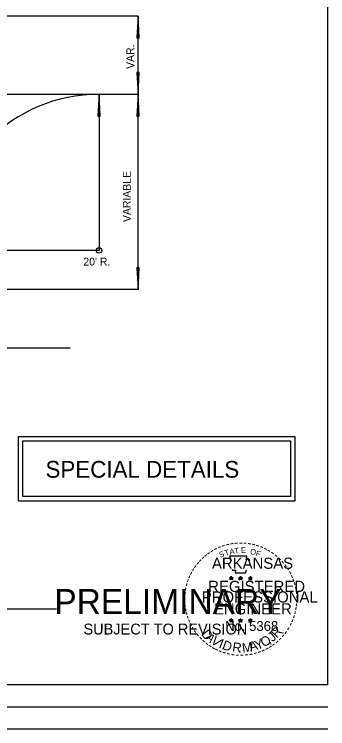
# Model space of a CAD drawing. Extents: x 1944905 to 1956777, y 763871 to 764977.
# Drawn here: x 1947951 to 1948232, y 763871 to 764511 of the extents above; entities that cross this region are included whole.
import ezdxf

# ---------------------------------------------------------------- set-up
doc = ezdxf.new("R2010")
doc.units = 0
for name, color, linetype in [('Default', 7, 'Continuous'), ('E_Existing ROW', 7, 'Continuous'), ('R_Border PE', 7, 'Continuous')]:
    doc.layers.add(name, color=color, linetype=linetype)

msp = doc.modelspace()

# ---------------------------------------------------------------- linework, layer by layer
at = {"layer": 'Default'}
for p, q in [((1948232.12, 763910.07), (1948232.12, 764937.29)), ((1948061.85, 764509.29), (1947543.85, 764509.29)), ((1948061.85, 764509.29), (1948060.88, 764489.74)), ((1948061.85, 764439.29), (1948061.85, 764509.29)), ((1948062.83, 764489.74), (1948061.85, 764509.29)), ((1948060.88, 764489.74), (1948062.83, 764489.74)), ((1948062.83, 764489.68), (1948062.83, 764489.74)), ((1948060.88, 764458.9), (1948060.88, 764458.84)), ((1948060.88, 764458.84), (1948061.85, 764439.29)), ((1948062.83, 764458.84), (1948060.88, 764458.84)), ((1948061.85, 764439.29), (1948062.83, 764458.84)), ((1947578.85, 764439.29), (1948026.85, 764439.29)), ((1948026.85, 764439.29), (1948025.88, 764419.74)), ((1948027.83, 764419.74), (1948026.85, 764439.29)), ((1948026.85, 764439.29), (1948026.85, 764299.29)), ((1948061.85, 764439.29), (1948060.88, 764419.74)), ((1948062.83, 764419.74), (1948061.85, 764439.29)), ((1948061.85, 764264.29), (1948061.85, 764438.7)), ((1948025.88, 764419.74), (1948027.83, 764419.74)), ((1948027.83, 764419.68), (1948027.83, 764419.74)), ((1948060.88, 764419.74), (1948062.83, 764419.74)), ((1948062.83, 764419.68), (1948062.83, 764419.74)), ((1948026.85, 764299.29), (1947886.85, 764299.29)), ((1948060.88, 764283.9), (1948060.88, 764283.84)), ((1948060.88, 764283.84), (1948061.85, 764264.29)), ((1948062.83, 764283.84), (1948060.88, 764283.84)), ((1948061.85, 764264.29), (1948062.83, 764283.84)), ((1948061.85, 764264.29), (1947886.85, 764264.29)), ((1947605.64, 764211.94), (1948001.01, 764211.94)), ((1947592.86, 763978), (1947988.57, 763978)), ((1948232.12, 763910.07), (1946651.22, 763910.07)), ((1946618.38, 763890.36), (1948232.12, 763890.36)), ((1946618.38, 763870.67), (1948232.12, 763870.67))]:
    msp.add_line(p, q, dxfattribs=at)
for points in [[(1947954.62, 764132.69), (1948202.63, 764132.69), (1948202.63, 764074.65), (1947954.62, 764074.65)], [(1947958.62, 764128.69), (1948198.63, 764128.69), (1948198.63, 764078.65), (1947958.62, 764078.65)]]:
    msp.add_lwpolyline(points, close=True, dxfattribs=at)
msp.add_circle((1948026.85, 764299.29), 2.44, dxfattribs=at)
at = {"layer": 'E_Existing ROW'}
msp.add_line((1948026.85, 764439.29), (1948061.85, 764439.29), dxfattribs=at)
msp.add_arc((1948026.85, 764299.29), 140, 90, 180, dxfattribs=at)
at = {"layer": 'R_Border PE'}
for p, q in [((1948143.78, 764006.04), (1948145.48, 764005.49)), ((1948143.78, 764006.04), (1948145.03, 764005.89)), ((1948143.78, 764006.04), (1948145.03, 764005.84)), ((1948143.78, 764006.04), (1948144.98, 764005.74)), ((1948143.78, 764006.04), (1948144.98, 764005.54)), ((1948143.78, 764006.04), (1948144.93, 764005.44)), ((1948143.78, 764006.04), (1948144.93, 764005.34)), ((1948144.43, 764003.99), (1948145.48, 764005.49)), ((1948144.43, 764003.99), (1948144.98, 764005.39)), ((1948144.43, 764003.99), (1948145.03, 764005.24)), ((1948144.43, 764003.99), (1948145.13, 764005.19)), ((1948144.43, 764003.99), (1948145.48, 764005.09)), ((1948144.43, 764003.99), (1948145.28, 764005.04)), ((1948144.43, 764003.99), (1948145.53, 764004.94)), ((1948145.48, 764007.29), (1948145.23, 764006.09)), ((1948145.48, 764007.29), (1948145.28, 764006.04)), ((1948145.48, 764007.29), (1948145.43, 764006.04)), ((1948145.48, 764005.49), (1948145.48, 764007.29)), ((1948145.48, 764007.29), (1948145.83, 764006.04)), ((1948145.48, 764007.29), (1948145.73, 764006.04)), ((1948145.48, 764007.29), (1948145.63, 764006.09)), ((1948147.23, 764006.04), (1948145.48, 764005.49)), ((1948146.58, 764003.99), (1948145.48, 764005.49)), ((1948146.58, 764003.99), (1948145.48, 764005.09)), ((1948146.58, 764003.99), (1948145.48, 764004.94)), ((1948146.58, 764003.99), (1948145.68, 764005.04)), ((1948147.23, 764006.04), (1948145.73, 764005.94)), ((1948147.23, 764006.04), (1948145.83, 764005.79)), ((1948147.23, 764006.04), (1948145.83, 764005.69)), ((1948146.58, 764003.99), (1948145.83, 764005.24)), ((1948146.58, 764003.99), (1948145.88, 764005.44)), ((1948146.58, 764003.99), (1948145.98, 764005.44)), ((1948147.23, 764006.04), (1948146.13, 764005.59)), ((1948147.23, 764006.04), (1948146.23, 764005.54)), ((1948147.23, 764006.04), (1948146.28, 764005.49)), ((1948152.08, 764006.04), (1948153.83, 764005.49)), ((1948152.08, 764006.04), (1948153.38, 764005.89)), ((1948152.08, 764006.04), (1948153.38, 764005.84)), ((1948152.08, 764006.04), (1948153.33, 764005.74)), ((1948152.08, 764006.04), (1948153.33, 764005.54)), ((1948152.08, 764006.04), (1948153.28, 764005.44)), ((1948152.08, 764006.04), (1948153.28, 764005.34)), ((1948152.78, 764003.99), (1948153.83, 764005.49)), ((1948152.78, 764003.99), (1948153.33, 764005.39)), ((1948152.78, 764003.99), (1948153.38, 764005.24)), ((1948152.78, 764003.99), (1948153.48, 764005.19)), ((1948152.78, 764003.99), (1948153.83, 764005.09)), ((1948152.78, 764003.99), (1948153.63, 764005.04)), ((1948152.78, 764003.99), (1948153.88, 764004.94)), ((1948153.83, 764007.29), (1948153.58, 764006.09)), ((1948153.83, 764007.29), (1948153.63, 764006.04)), ((1948153.83, 764007.29), (1948153.78, 764006.04)), ((1948153.83, 764005.49), (1948153.83, 764007.29)), ((1948153.83, 764007.29), (1948154.18, 764006.04)), ((1948153.83, 764007.29), (1948154.08, 764006.04)), ((1948153.83, 764007.29), (1948153.98, 764006.09)), ((1948155.58, 764006.04), (1948153.83, 764005.49)), ((1948154.93, 764003.99), (1948153.83, 764005.49)), ((1948154.93, 764003.99), (1948153.83, 764005.09)), ((1948154.93, 764003.99), (1948153.83, 764004.94)), ((1948155.58, 764006.04), (1948154.03, 764005.94)), ((1948154.93, 764003.99), (1948154.03, 764005.04)), ((1948155.58, 764006.04), (1948154.13, 764005.79)), ((1948155.58, 764006.04), (1948154.13, 764005.69)), ((1948154.93, 764003.99), (1948154.18, 764005.24)), ((1948154.93, 764003.99), (1948154.23, 764005.44)), ((1948154.93, 764003.99), (1948154.33, 764005.44)), ((1948155.58, 764006.04), (1948154.48, 764005.59)), ((1948155.58, 764006.04), (1948154.58, 764005.54)), ((1948155.58, 764006.04), (1948154.63, 764005.49)), ((1948160.93, 764005.99), (1948162.68, 764005.44)), ((1948160.93, 764005.99), (1948162.23, 764005.84)), ((1948160.93, 764005.99), (1948162.23, 764005.74)), ((1948160.93, 764005.99), (1948162.18, 764005.64)), ((1948160.93, 764005.99), (1948162.13, 764005.49)), ((1948160.93, 764005.99), (1948162.13, 764005.39)), ((1948160.93, 764005.99), (1948162.13, 764005.29)), ((1948161.63, 764003.94), (1948162.68, 764005.44)), ((1948161.63, 764003.94), (1948162.18, 764005.34)), ((1948161.63, 764003.94), (1948162.23, 764005.14)), ((1948161.63, 764003.94), (1948162.33, 764005.14)), ((1948161.63, 764003.94), (1948162.68, 764005.04)), ((1948161.63, 764003.94), (1948162.48, 764004.99)), ((1948161.63, 764003.94), (1948162.73, 764004.89)), ((1948162.68, 764007.24), (1948162.38, 764006.04)), ((1948162.68, 764007.24), (1948162.48, 764005.99)), ((1948162.68, 764007.24), (1948162.58, 764005.99)), ((1948162.68, 764005.44), (1948162.68, 764007.24)), ((1948162.68, 764007.24), (1948163.03, 764005.99)), ((1948162.68, 764007.24), (1948162.93, 764005.99)), ((1948162.68, 764007.24), (1948162.78, 764006.04)), ((1948164.43, 764005.99), (1948162.68, 764005.44)), ((1948163.73, 764003.94), (1948162.68, 764005.44)), ((1948163.73, 764003.94), (1948162.68, 764005.04)), ((1948163.73, 764003.94), (1948162.68, 764004.89)), ((1948164.43, 764005.99), (1948162.88, 764005.89)), ((1948163.73, 764003.94), (1948162.88, 764004.99)), ((1948164.43, 764005.99), (1948162.98, 764005.74)), ((1948164.43, 764005.99), (1948162.98, 764005.64)), ((1948163.73, 764003.94), (1948163.03, 764005.19)), ((1948163.73, 764003.94), (1948163.08, 764005.39)), ((1948163.73, 764003.94), (1948163.18, 764005.39)), ((1948164.43, 764005.99), (1948163.33, 764005.54)), ((1948164.43, 764005.99), (1948163.38, 764005.49)), ((1948164.43, 764005.99), (1948163.48, 764005.44)), ((1948143.73, 763968.19), (1948145.48, 763967.64)), ((1948143.73, 763968.19), (1948145.03, 763968.04)), ((1948143.73, 763968.19), (1948145.03, 763967.94)), ((1948143.73, 763968.19), (1948144.98, 763967.84)), ((1948143.73, 763968.19), (1948144.93, 763967.69)), ((1948143.73, 763968.19), (1948144.93, 763967.59)), ((1948143.73, 763968.19), (1948144.93, 763967.44)), ((1948144.43, 763966.14), (1948145.48, 763967.64)), ((1948144.43, 763966.14), (1948144.98, 763967.54)), ((1948144.43, 763966.14), (1948145.03, 763967.34)), ((1948144.43, 763966.14), (1948145.13, 763967.29)), ((1948144.43, 763966.14), (1948145.48, 763967.24)), ((1948144.43, 763966.14), (1948145.28, 763967.19)), ((1948144.43, 763966.14), (1948145.53, 763967.09)), ((1948145.48, 763969.44), (1948145.18, 763968.24)), ((1948145.48, 763969.44), (1948145.28, 763968.19)), ((1948145.48, 763969.44), (1948145.38, 763968.19)), ((1948145.48, 763967.64), (1948145.48, 763969.44)), ((1948145.48, 763969.44), (1948145.83, 763968.19)), ((1948145.48, 763969.44), (1948145.73, 763968.19)), ((1948145.48, 763969.44), (1948145.58, 763968.19)), ((1948147.23, 763968.19), (1948145.48, 763967.64)), ((1948146.53, 763966.14), (1948145.48, 763967.64)), ((1948146.53, 763966.14), (1948145.48, 763967.19)), ((1948146.53, 763966.14), (1948145.48, 763967.09)), ((1948147.23, 763968.19), (1948145.68, 763968.09)), ((1948146.53, 763966.14), (1948145.68, 763967.19)), ((1948147.23, 763968.19), (1948145.78, 763967.94)), ((1948147.23, 763968.19), (1948145.78, 763967.84)), ((1948146.53, 763966.14), (1948145.83, 763967.34)), ((1948146.53, 763966.14), (1948145.88, 763967.59)), ((1948146.53, 763966.14), (1948145.98, 763967.59)), ((1948147.23, 763968.19), (1948146.13, 763967.74)), ((1948147.23, 763968.19), (1948146.18, 763967.69)), ((1948147.23, 763968.19), (1948146.28, 763967.59)), ((1948152.08, 763968.19), (1948153.83, 763967.64)), ((1948152.08, 763968.19), (1948153.38, 763968.04)), ((1948152.08, 763968.19), (1948153.33, 763967.94)), ((1948152.08, 763968.19), (1948153.33, 763967.84)), ((1948152.08, 763968.19), (1948153.28, 763967.69)), ((1948152.08, 763968.19), (1948153.28, 763967.59)), ((1948152.08, 763968.19), (1948153.28, 763967.44)), ((1948152.73, 763966.14), (1948153.83, 763967.64)), ((1948152.73, 763966.14), (1948153.33, 763967.54)), ((1948152.73, 763966.14), (1948153.38, 763967.34)), ((1948152.73, 763966.14), (1948153.48, 763967.29)), ((1948152.73, 763966.14), (1948153.83, 763967.24)), ((1948152.73, 763966.14), (1948153.63, 763967.19)), ((1948152.73, 763966.14), (1948153.83, 763967.09)), ((1948153.83, 763969.44), (1948153.53, 763968.24)), ((1948153.83, 763969.44), (1948153.63, 763968.19)), ((1948153.83, 763969.44), (1948153.73, 763968.19)), ((1948153.83, 763967.64), (1948153.83, 763969.44)), ((1948153.83, 763969.44), (1948154.18, 763968.19)), ((1948153.83, 763969.44), (1948154.08, 763968.19)), ((1948153.83, 763969.44), (1948153.93, 763968.19)), ((1948155.58, 763968.19), (1948153.83, 763967.64)), ((1948154.88, 763966.14), (1948153.83, 763967.64)), ((1948154.88, 763966.14), (1948153.83, 763967.19)), ((1948154.88, 763966.14), (1948153.83, 763967.09)), ((1948155.58, 763968.19), (1948154.03, 763968.09)), ((1948154.88, 763966.14), (1948154.03, 763967.19)), ((1948155.58, 763968.19), (1948154.13, 763967.94)), ((1948155.58, 763968.19), (1948154.13, 763967.84)), ((1948154.88, 763966.14), (1948154.18, 763967.34)), ((1948154.88, 763966.14), (1948154.23, 763967.59)), ((1948154.88, 763966.14), (1948154.33, 763967.59)), ((1948155.58, 763968.19), (1948154.43, 763967.74)), ((1948155.58, 763968.19), (1948154.53, 763967.69)), ((1948155.58, 763968.19), (1948154.63, 763967.59)), ((1948160.93, 763968.14), (1948162.68, 763967.54)), ((1948160.93, 763968.14), (1948162.18, 763967.99)), ((1948160.93, 763968.14), (1948162.18, 763967.89)), ((1948160.93, 763968.14), (1948162.13, 763967.79)), ((1948160.93, 763968.14), (1948162.13, 763967.64)), ((1948160.93, 763968.14), (1948162.08, 763967.49)), ((1948160.93, 763968.14), (1948162.08, 763967.39)), ((1948161.58, 763966.09), (1948162.68, 763967.54)), ((1948161.58, 763966.09), (1948162.13, 763967.44)), ((1948161.58, 763966.09), (1948162.23, 763967.29)), ((1948161.58, 763966.09), (1948162.33, 763967.24)), ((1948161.58, 763966.09), (1948162.48, 763967.14)), ((1948161.58, 763966.09), (1948162.63, 763967.14)), ((1948161.58, 763966.09), (1948162.68, 763967.04)), ((1948162.68, 763969.39), (1948162.38, 763968.14)), ((1948162.68, 763969.39), (1948162.48, 763968.14)), ((1948162.68, 763969.39), (1948162.58, 763968.14)), ((1948163.73, 763966.09), (1948162.63, 763967.14)), ((1948163.73, 763966.09), (1948162.63, 763966.99)), ((1948162.68, 763967.54), (1948162.68, 763969.39)), ((1948162.68, 763969.39), (1948162.98, 763968.14)), ((1948162.68, 763969.39), (1948162.93, 763968.14)), ((1948162.68, 763969.39), (1948162.78, 763968.14)), ((1948164.38, 763968.14), (1948162.68, 763967.54)), ((1948163.73, 763966.09), (1948162.68, 763967.54)), ((1948163.73, 763966.09), (1948162.83, 763967.14)), ((1948164.38, 763968.14), (1948162.88, 763967.99)), ((1948164.38, 763968.14), (1948162.98, 763967.89)), ((1948164.38, 763968.14), (1948162.98, 763967.79)), ((1948163.73, 763966.09), (1948163.03, 763967.54)), ((1948163.73, 763966.09), (1948163.03, 763967.29)), ((1948163.73, 763966.09), (1948163.18, 763967.54)), ((1948164.38, 763968.14), (1948163.28, 763967.64)), ((1948164.38, 763968.14), (1948163.38, 763967.59)), ((1948164.38, 763968.14), (1948163.43, 763967.54))]:
    msp.add_line(p, q, dxfattribs=at)
for points in [[(1948143.98, 764025.44), (1948145.33, 764021.29)], [(1948161.53, 764020.84), (1948162.23, 764022.24), (1948158.78, 764022.14), (1948159.53, 764025.44), (1948143.98, 764025.44)], [(1948146.43, 764013.34), (1948146.43, 764012.89), (1948149.23, 764012.79), (1948148.98, 764010.44), (1948158.33, 764010.44), (1948159.33, 764013.09)], [(1948145.48, 764007.29), (1948146.58, 764003.99), (1948143.78, 764006.04), (1948147.23, 764006.04), (1948144.43, 764003.99), (1948145.48, 764007.29)], [(1948153.83, 764007.29), (1948154.93, 764003.99), (1948152.08, 764006.04), (1948155.58, 764006.04), (1948152.78, 764003.99), (1948153.83, 764007.29)], [(1948162.68, 764007.24), (1948163.73, 764003.94), (1948160.93, 764005.99), (1948164.43, 764005.99), (1948161.63, 764003.94), (1948162.68, 764007.24)], [(1948145.48, 763969.44), (1948146.53, 763966.14), (1948143.73, 763968.19), (1948147.23, 763968.19), (1948144.43, 763966.14), (1948145.48, 763969.44)], [(1948153.83, 763969.44), (1948154.88, 763966.14), (1948152.08, 763968.19), (1948155.58, 763968.19), (1948152.73, 763966.14), (1948153.83, 763969.44)], [(1948162.68, 763969.39), (1948163.73, 763966.09), (1948160.93, 763968.14), (1948164.38, 763968.14), (1948161.58, 763966.09), (1948162.68, 763969.39)]]:
    msp.add_lwpolyline(points, dxfattribs=at)
for centre, radius in [((1948145.48, 764005.49), 0.861), ((1948145.48, 764005.49), 0.78), ((1948145.48, 764005.49), 0.723), ((1948145.48, 764005.49), 0.664), ((1948145.48, 764005.49), 0.579), ((1948145.48, 764005.49), 0.537), ((1948145.48, 764005.49), 0.495), ((1948145.48, 764005.49), 0.426), ((1948145.48, 764005.49), 0.374), ((1948145.48, 764005.49), 0.311), ((1948145.48, 764005.49), 0.248), ((1948145.48, 764005.49), 0.185), ((1948145.48, 764005.49), 0.148), ((1948145.48, 764005.49), 0.0721), ((1948153.83, 764005.49), 0.861), ((1948153.83, 764005.49), 0.78), ((1948153.83, 764005.49), 0.723), ((1948153.83, 764005.49), 0.664), ((1948153.83, 764005.49), 0.579), ((1948153.83, 764005.49), 0.537), ((1948153.83, 764005.49), 0.495), ((1948153.83, 764005.49), 0.426), ((1948153.83, 764005.49), 0.374), ((1948153.83, 764005.49), 0.311), ((1948153.83, 764005.49), 0.248), ((1948153.83, 764005.49), 0.185), ((1948153.83, 764005.49), 0.148), ((1948153.83, 764005.49), 0.0721), ((1948162.66, 764005.43), 0.861), ((1948162.66, 764005.43), 0.78), ((1948162.66, 764005.43), 0.723), ((1948162.66, 764005.43), 0.664), ((1948162.66, 764005.43), 0.579), ((1948162.66, 764005.43), 0.537), ((1948162.66, 764005.43), 0.495), ((1948162.66, 764005.43), 0.426), ((1948162.66, 764005.43), 0.374), ((1948162.66, 764005.43), 0.311), ((1948162.66, 764005.43), 0.248), ((1948162.66, 764005.43), 0.185), ((1948162.66, 764005.43), 0.148), ((1948162.66, 764005.43), 0.0721), ((1948145.46, 763967.63), 0.861), ((1948145.46, 763967.63), 0.78), ((1948145.46, 763967.63), 0.723), ((1948145.46, 763967.63), 0.664), ((1948145.46, 763967.63), 0.579), ((1948145.46, 763967.63), 0.537), ((1948145.46, 763967.63), 0.495), ((1948145.46, 763967.63), 0.426), ((1948145.46, 763967.63), 0.374), ((1948145.46, 763967.63), 0.311), ((1948145.46, 763967.63), 0.248), ((1948145.46, 763967.63), 0.185), ((1948145.46, 763967.63), 0.148), ((1948145.46, 763967.63), 0.0721), ((1948153.81, 763967.63), 0.861), ((1948153.81, 763967.63), 0.78), ((1948153.81, 763967.63), 0.723), ((1948153.81, 763967.63), 0.664), ((1948153.81, 763967.63), 0.579), ((1948153.81, 763967.63), 0.537), ((1948153.81, 763967.63), 0.495), ((1948153.81, 763967.63), 0.426), ((1948153.81, 763967.63), 0.374), ((1948153.81, 763967.63), 0.311), ((1948153.81, 763967.63), 0.248), ((1948153.81, 763967.63), 0.185), ((1948153.81, 763967.63), 0.148), ((1948153.81, 763967.63), 0.0721), ((1948162.64, 763967.57), 0.861), ((1948162.64, 763967.57), 0.78), ((1948162.64, 763967.57), 0.723), ((1948162.64, 763967.57), 0.664), ((1948162.64, 763967.57), 0.579), ((1948162.64, 763967.57), 0.537), ((1948162.64, 763967.57), 0.495), ((1948162.64, 763967.57), 0.426), ((1948162.64, 763967.57), 0.374), ((1948162.64, 763967.57), 0.311), ((1948162.64, 763967.57), 0.248), ((1948162.64, 763967.57), 0.185), ((1948162.64, 763967.57), 0.148), ((1948162.64, 763967.57), 0.0721)]:
    msp.add_circle(centre, radius, dxfattribs=at)

# ---------------------------------------------------------------- texts
at = {"layer": 'Default'}
for s, p in [('VAR.', (1948058.43, 764462.01)), ('VARIABLE', (1948055.31, 764324.75))]:
    msp.add_text(s, height=7, rotation=90, dxfattribs=at).set_placement(p)
for s, height, p in [("20' R.", 7, (1948012.8, 764285.79)), ('SPECIAL DETAILS', 15, (1947978.81, 764095.64)), ('PRELIMINARY', 22.5, (1947986.71, 763973.37)), ('        SUBJECT TO REVISION', 9.75, (1947983.89, 763955.1))]:
    msp.add_text(s, height=height, dxfattribs=at).set_placement(p)
at = {"layer": 'R_Border PE'}
for s, height, rotation, p in [('-', 8, 13.63015, (1948141.43, 764032.29)), ('-', 8, 10.21935, (1948144.83, 764033.09)), ('-', 8, 5.89682, (1948148.48, 764033.64)), ('-', 8, 0.18623, (1948152.33, 764033.99)), ('-', 8, 357.74304, (1948155.98, 764033.94)), ('-', 8, 352.16173, (1948159.68, 764033.64)), ('-', 8, 347.20489, (1948163.28, 764033.09)), ('-', 8, 34.06357, (1948128.38, 764026.29)), ('-', 8, 28.79182, (1948131.38, 764028.14)), ('-', 8, 24.30721, (1948134.53, 764029.74)), ('-', 8, 19.17608, (1948137.68, 764031.09)), ('T', 5, 16.4036, (1948140.33, 764025.49)), ('A', 5, 11.21318, (1948144.43, 764026.74)), ('T', 5, 6.02276, (1948148.68, 764027.54)), ('E', 5, 0.83234, (1948154.23, 764028.09)), ('O', 5, 350.4515, (1948162.23, 764027.04)), ('F', 5, 340.07066, (1948166.98, 764025.94)), ('-', 8, 342.3362, (1948166.43, 764032.29)), ('-', 8, 337.85509, (1948170.13, 764031.19)), ('-', 8, 334.12109, (1948173.28, 764029.84)), ('-', 8, 329.64089, (1948176.18, 764028.44)), ('-', 8, 42.96224, (1948120.93, 764020.34)), ('-', 8, 38.95066, (1948123.13, 764022.44)), ('-', 8, 36.23174, (1948125.48, 764024.29)), ('S', 5, 21.59401, (1948135.73, 764023.84)), ('-', 8, 325.86266, (1948179.38, 764026.59)), ('-', 8, 320.52971, (1948182.43, 764024.49)), ('-', 8, 315.57859, (1948185.43, 764022.04)), ('-', 8, 54.23247, (1948114.63, 764012.69)), ('-', 8, 50.61417, (1948116.68, 764015.54)), ('-', 8, 48.42305, (1948118.73, 764017.94)), ('-', 8, 309.87973, (1948188.28, 764019.29)), ('-', 8, 306.65218, (1948190.93, 764016.29)), ('-', 8, 62.87135, (1948111.43, 764006.99)), ('-', 8, 58.07063, (1948112.98, 764010.04)), ('-', 7, 303.67529, (1948193.33, 764013.44)), ('-', 8, 299.66835, (1948194.93, 764010.39)), ('-', 8, 72.39447, (1948109.03, 764000.79)), ('-', 8, 67.77427, (1948110.13, 764003.94)), ('-', 8, 294.66279, (1948196.53, 764007.34)), ('-', 8, 290.57283, (1948197.83, 764004.44)), ('-', 8, 75.46096, (1948108.08, 763997.19)), ('-', 8, 285.12326, (1948199.03, 764001.54)), ('-', 8, 280.54934, (1948200.03, 763997.84)), ('-', 8, 85.18634, (1948107.03, 763990.19)), ('-', 8, 81.20126, (1948107.38, 763993.64)), ('-', 8, 276.59616, (1948200.83, 763993.99)), ('-', 8, 94.19588, (1948107.08, 763983.04)), ('-', 8, 89.06224, (1948106.88, 763986.69)), ('-', 8, 274.33011, (1948201.13, 763990.39)), ('-', 8, 269.94067, (1948201.28, 763987.24)), ('-', 8, 98.94793, (1948107.43, 763979.74)), ('-', 8, 260.99529, (1948200.83, 763980.64)), ('-', 8, 263.5172, (1948201.18, 763983.89)), ('-', 8, 101.71495, (1948108.13, 763976.04)), ('-', 8, 105.45785, (1948108.93, 763973.09)), ('-', 8, 252.86809, (1948199.38, 763973.64)), ('-', 8, 255.7626, (1948200.28, 763977.24)), ('-', 8, 109.08742, (1948109.98, 763969.94)), ('-', 8, 114.06432, (1948111.28, 763966.94)), ('-', 8, 247.88866, (1948198.28, 763970.29)), ('-', 8, 115.72885, (1948112.78, 763963.84)), ('-', 8, 120.44712, (1948114.58, 763960.94)), ('D', 8.47, 308.02669, (1948118.13, 763955.44)), ('R', 8.47, 46.29225, (1948186.23, 763951.44)), ('-', 8, 239.07125, (1948194.98, 763963.39)), ('-', 8, 244.61971, (1948196.98, 763967.14)), ('-', 8, 125.89344, (1948116.58, 763958.14)), ('-', 8, 130.71812, (1948118.88, 763955.34)), ('-', 8, 134.22381, (1948121.48, 763952.64)), ('A', 7.7, 314.16829, (1948121.88, 763951.99)), ('V', 8.47, 322.07513, (1948126.53, 763947.94)), ('O', 8.47, 27.86746, (1948174.48, 763943.49)), ('J', 8.47, 40.15065, (1948182.48, 763948.09)), ('-', 8, 231.25377, (1948190.83, 763957.29)), ('-', 8, 233.84524, (1948192.98, 763960.14)), ('-', 8, 138.93382, (1948124.13, 763950.29)), ('-', 8, 144.64634, (1948126.88, 763948.29)), ('ID', 8.47, 339.24466, (1948133.78, 763943.49)), ('R', 8.47, 351.48461, (1948146.08, 763939.94)), ('M', 8.47, 7.38422, (1948155.78, 763938.79)), ('A', 8.47, 15.04444, (1948162.78, 763939.74)), ('Y', 8.47, 21.72586, (1948168.58, 763941.09)), (',', 8.45, 13.66842, (1948179.33, 763946.74)), ('-', 8, 215.73633, (1948183.08, 763949.54)), ('-', 8, 221.08509, (1948185.83, 763951.94)), ('-', 8, 225.76533, (1948188.43, 763954.49)), ('-', 8, 148.08978, (1948129.68, 763946.44)), ('-', 8, 151.57039, (1948132.58, 763944.79)), ('-', 8, 154.60019, (1948135.18, 763943.59)), ('-', 8, 158.56121, (1948138.33, 763942.29)), ('-', 8, 200.71842, (1948171.38, 763942.94)), ('-', 8, 204.25161, (1948174.48, 763944.29)), ('-', 8, 207.35684, (1948177.63, 763945.89)), ('-', 8, 212.24909, (1948180.43, 763947.64)), ('-', 8, 162.79826, (1948141.73, 763941.24)), ('-', 8, 167.55551, (1948145.33, 763940.39)), ('-', 8, 173.11546, (1948149.18, 763939.84)), ('-', 8, 176.51827, (1948152.93, 763939.59)), ('.', 7.7, 351.01787, (1948151.88, 763938.99)), ('-', 8, 181.59176, (1948156.63, 763939.69)), ('-', 8, 185.81666, (1948160.68, 763940.09)), ('-', 8, 191.28576, (1948164.38, 763940.74)), ('-', 8, 195.47429, (1948168.03, 763941.74))]:
    msp.add_text(s, height=height, rotation=rotation, dxfattribs=at).set_placement(p)
for s, height, p in [('ARKANSAS', 10, (1948128.23, 764013.99)), ('REGISTERED', 10, (1948124.83, 763993.24)), ('PROFESSIONAL', 9.9999, (1948119.08, 763983.74)), ('ENGINEER', 10, (1948130.03, 763973.09)), ('No. 5368', 8.785, (1948140.03, 763958.34)), ('.', 8.45, (1948190.28, 763955.84))]:
    msp.add_text(s, height=height, dxfattribs=at).set_placement(p)

doc.saveas('drawing.dxf')
